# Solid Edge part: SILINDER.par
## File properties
Author: Türk
Template: iso part.par
Last saved by: Türk
Revision: 44
Application: Solid Edge
Accuracy: 0,990
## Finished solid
Body 1: sheet body, 2 faces, 150 edges, 150 vertices.
  Faces by surface: plane 2
  Edges by curve: line 102, circle 48
Body 2: sheet body, 2 faces, 76 edges, 76 vertices.
  Faces by surface: plane 2
  Edges by curve: line 52, intersection 20, circle 4
Body 3: solid body, 274 faces, 784 edges, 516 vertices.
  Faces by surface: cylinder 149, plane 101, cone 14, torus 10
  Edges by curve: line 374, circle 335, intersection 74, ellipse 1
Bounding box of the edges (mm; curved faces can reach further): 640.000 x 347.698 x 213.551, from (-320, -127.6984, -111.7187) to (320, 220, 101.8327).
Cylindrical faces by radius (mm): R7 x20, R10 x36, R15 x8, R22 x6, R44 x5, R50 x24, R70 x18, R78 x4, R80 x8, R82.5 x10, R90 x10
Conical faces (half-angle, radius in mm at the cone's reference point): 6 deg R80 x4, 45 deg R90 x10
Toroidal faces (ring radius, tube radius in mm): R77.5 r5 x10
Planar faces by outward normal: +x 18, +y 23, +z 16, -x 17, -y 4, -z 16, oblique 7
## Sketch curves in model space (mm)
line (0, 48.4062, 34.6876) -> (0, 48.4062, -36.2077)
arc centre (201, -20, 77.5) radius 5 from (201, -20, 82.5) through (197.3631, -20, 80.9312) to (196, -20, 77.5)
line (-320, -20, 58.7298) -> (-320, -20, 22)
arc centre (-201, -20, 77.5) radius 5 from (-201, -20, 82.5) through (-197.3631, -20, 80.9312) to (-196, -20, 77.5)
arc centre (39, -20, 77.5) radius 5 from (39, -20, 82.5) through (42.6369, -20, 80.9312) to (44, -20, 77.5)
line (-320, -20, -58.7298) -> (-320, -20, -22)
line (200, -20, -85) -> (200, -20, -82.399)
arc centre (201, -20, -77.5) radius 5 from (200, -20, -82.399) through (200.4975, -20, -82.4747) to (201, -20, -82.5)
line (315, -20, -24) -> (315, -20, -22)
line (315, -20, -24) -> (286, -20, -24)
line (286, -20, -24) -> (286, -20, -77.5)
arc centre (279, -20, -77.5) radius 7 from (286, -20, -77.5) through (283.8037, -20, -82.5916) to (279, -20, -84.5)
line (279, -20, -84.5) -> (201, -20, -84.5)
arc centre (201, -20, -77.5) radius 7 from (201, -20, -84.5) through (195.9084, -20, -82.3037) to (194, -20, -77.5)
line (194, -20, -77.5) -> (194, -20, -24)
line (194, -20, -24) -> (166, -20, -24)
line (166, -20, -24) -> (166, -20, -77.5)
arc centre (159, -20, -77.5) radius 7 from (166, -20, -77.5) through (163.8037, -20, -82.5916) to (159, -20, -84.5)
line (159, -20, -84.5) -> (81, -20, -84.5)
arc centre (81, -20, -77.5) radius 7 from (81, -20, -84.5) through (75.9084, -20, -82.3037) to (74, -20, -77.5)
line (74, -20, -77.5) -> (74, -20, -24)
line (74, -20, -24) -> (46, -20, -24)
line (46, -20, -24) -> (46, -20, -77.5)
arc centre (39, -20, -77.5) radius 7 from (46, -20, -77.5) through (43.8037, -20, -82.5916) to (39, -20, -84.5)
line (39, -20, -84.5) -> (-39, -20, -84.5)
arc centre (-39, -20, -77.5) radius 7 from (-39, -20, -84.5) through (-44.0916, -20, -82.3037) to (-46, -20, -77.5)
line (-46, -20, -77.5) -> (-46, -20, -24)
line (-46, -20, -24) -> (-74, -20, -24)
line (-74, -20, -24) -> (-74, -20, -77.5)
arc centre (-81, -20, -77.5) radius 7 from (-74, -20, -77.5) through (-76.1963, -20, -82.5916) to (-81, -20, -84.5)
line (-81, -20, -84.5) -> (-159, -20, -84.5)
arc centre (-159, -20, -77.5) radius 7 from (-159, -20, -84.5) through (-164.0916, -20, -82.3037) to (-166, -20, -77.5)
line (-166, -20, -77.5) -> (-166, -20, -24)
line (-166, -20, -24) -> (-194, -20, -24)
line (-194, -20, -24) -> (-194, -20, -77.5)
arc centre (-201, -20, -77.5) radius 7 from (-194, -20, -77.5) through (-196.1963, -20, -82.5916) to (-201, -20, -84.5)
line (-201, -20, -84.5) -> (-279, -20, -84.5)
arc centre (-279, -20, -77.5) radius 7 from (-279, -20, -84.5) through (-284.0916, -20, -82.3037) to (-286, -20, -77.5)
line (-286, -20, -77.5) -> (-286, -20, -24)
line (-286, -20, -24) -> (-318, -20, -24)
line (-318, -20, -24) -> (-318, -20, -58.2099)
arc centre (-250, -20, -20) radius 78 from (-318, -20, -58.2099) through (-289.393, -20, -87.3215) to (-250, -20, -98)
line (-250, -20, -98) -> (250, -20, -98)
arc centre (250, -20, -20) radius 78 from (250, -20, -98) through (286.8846, -20, -88.7279) to (315, -20, -63.1161)
line (315, -20, -66.6369) -> (315, -20, -63.1161)
line (315, -20, 63.1161) -> (315, -20, 66.6369)
arc centre (250, -20, 20) radius 78 from (250, -20, 98) through (286.8846, -20, 88.7279) to (315, -20, 63.1161)
line (-250, -20, 98) -> (250, -20, 98)
arc centre (-250, -20, 20) radius 78 from (-318, -20, 58.2099) through (-289.393, -20, 87.3215) to (-250, -20, 98)
line (-318, -20, 24) -> (-318, -20, 58.2099)
line (-286, -20, 24) -> (-318, -20, 24)
line (-286, -20, 77.5) -> (-286, -20, 24)
arc centre (-279, -20, 77.5) radius 7 from (-279, -20, 84.5) through (-284.0916, -20, 82.3037) to (-286, -20, 77.5)
line (-201, -20, 84.5) -> (-279, -20, 84.5)
arc centre (-201, -20, 77.5) radius 7 from (-194, -20, 77.5) through (-196.1963, -20, 82.5916) to (-201, -20, 84.5)
line (-194, -20, 24) -> (-194, -20, 77.5)
line (-166, -20, 24) -> (-194, -20, 24)
line (-166, -20, 77.5) -> (-166, -20, 24)
arc centre (-159, -20, 77.5) radius 7 from (-159, -20, 84.5) through (-164.0916, -20, 82.3037) to (-166, -20, 77.5)
line (-81, -20, 84.5) -> (-159, -20, 84.5)
arc centre (-81, -20, 77.5) radius 7 from (-74, -20, 77.5) through (-76.1963, -20, 82.5916) to (-81, -20, 84.5)
line (-74, -20, 24) -> (-74, -20, 77.5)
line (-46, -20, 24) -> (-74, -20, 24)
line (-46, -20, 77.5) -> (-46, -20, 24)
arc centre (-39, -20, 77.5) radius 7 from (-39, -20, 84.5) through (-44.0916, -20, 82.3037) to (-46, -20, 77.5)
line (39, -20, 84.5) -> (-39, -20, 84.5)
arc centre (39, -20, 77.5) radius 7 from (46, -20, 77.5) through (43.8037, -20, 82.5916) to (39, -20, 84.5)
line (46, -20, 24) -> (46, -20, 77.5)
line (74, -20, 24) -> (46, -20, 24)
line (74, -20, 77.5) -> (74, -20, 24)
arc centre (81, -20, 77.5) radius 7 from (81, -20, 84.5) through (75.9084, -20, 82.3037) to (74, -20, 77.5)
line (159, -20, 84.5) -> (81, -20, 84.5)
arc centre (159, -20, 77.5) radius 7 from (166, -20, 77.5) through (163.8037, -20, 82.5916) to (159, -20, 84.5)
line (166, -20, 24) -> (166, -20, 77.5)
line (194, -20, 24) -> (166, -20, 24)
line (194, -20, 77.5) -> (194, -20, 24)
arc centre (201, -20, 77.5) radius 7 from (201, -20, 84.5) through (195.9084, -20, 82.3037) to (194, -20, 77.5)
line (279, -20, 84.5) -> (201, -20, 84.5)
arc centre (279, -20, 77.5) radius 7 from (286, -20, 77.5) through (283.8037, -20, 82.5916) to (279, -20, 84.5)
line (286, -20, 24) -> (286, -20, 77.5)
line (315, -20, 24) -> (286, -20, 24)
line (315, -20, 22) -> (315, -20, 24)
arc centre (0, 145, 0) radius 80 from (-60, 145, -52.915) through (2.3391, 145, -79.9658) to (60, 145, -52.915)
arc centre (0, 145, 0) radius 80 from (60, 145, -52.915) through (-2.3391, 145, -79.9658) to (-60, 145, -52.915)
arc centre (0, 145, 0) radius 80 from (60, 145, 52.915) through (-2.3391, 145, 79.9658) to (-60, 145, 52.915)
arc centre (0, 145, 0) radius 80 from (60, 145, -52.915) through (-2.3391, 145, -79.9658) to (-60, 145, -52.915)
arc centre (0, 145, 0) radius 80 from (-60, 145, -52.915) through (2.3391, 145, -79.9658) to (60, 145, -52.915)
arc centre (0, 145, 0) radius 80 from (-60, 145, 52.915) through (2.3391, 145, 79.9658) to (60, 145, 52.915)
arc centre (-120, 145, 0) radius 80 from (-180, 145, -52.915) through (-117.6609, 145, -79.9658) to (-60, 145, -52.915)
arc centre (-120, 145, 0) radius 80 from (-60, 145, 52.915) through (-122.3391, 145, 79.9658) to (-180, 145, 52.915)
arc centre (-240, 145, 0) radius 80 from (-180, 145, 52.915) through (-319.4299, 145, -9.5333) to (-180, 145, -52.915)
arc centre (120, 145, 0) radius 80 from (180, 145, -52.915) through (117.6609, 145, -79.9658) to (60, 145, -52.915)
arc centre (120, 145, 0) radius 80 from (60, 145, 52.915) through (122.3391, 145, 79.9658) to (180, 145, 52.915)
arc centre (240, 145, 0) radius 80 from (180, 145, 52.915) through (319.4299, 145, -9.5333) to (180, 145, -52.915)
line (-320, -20, 0) -> (-320, 71.59, 0)
line (-320, 71.59, 0) -> (-320, 71.59, -19.9042)
line (-320, 110, 0) -> (-320, 155, 0)
line (-320, 71.59, 0) -> (-320, 110, 0)
line (270, 0, 0) -> (270, -50.7773, 108.8922)
arc centre (-244.8082, 0, 20) radius 44 from (-284, 0, 0) through (-234.5232, 0, -22.7811) to (-200.8082, 0, 20)
arc centre (240, 0, 0) radius 44 from (196, 0, 0) through (241.3039, 0, -43.9807) to (284, 0, 0)
arc centre (120, 0, 0) radius 44 from (80.8082, 0, 20) through (77.2189, 0, 10.2849) to (76, 0, 0)
arc centre (-120, 0, 0) radius 44 from (-76, 0, 0) through (-77.2189, 0, 10.2849) to (-80.8082, 0, 20)
arc centre (0, 0, 0) radius 44 from (44, 0, 0) through (42.7811, 0, 10.2849) to (39.1918, 0, 20)
arc centre (120, 0, 0) radius 80 from (60, 0, -52.915) through (122.3391, 0, -79.9658) to (180, 0, -52.915)
arc centre (-240, 0, 0) radius 80 from (-180, 0, -52.915) through (-319.4299, 0, 9.5333) to (-180, 0, 52.915)
arc centre (-120, 0, 0) radius 80 from (-60, 0, -52.915) through (-122.3391, 0, -79.9658) to (-180, 0, -52.915)
arc centre (0, 0, 0) radius 80 from (0, 0, -80) through (-32.915, 0, -72.915) to (-60, 0, -52.915)
arc centre (0, 0, 0) radius 80 from (0, 0, -80) through (32.915, 0, -72.915) to (60, 0, -52.915)
circle centre (-240, 0, 0) radius 44.5
circle centre (-120, 0, 0) radius 44.5
circle centre (-240, 0, 0) radius 47.5
circle centre (-120, 0, 0) radius 47.5
circle centre (240, 0, 0) radius 44.5
circle centre (120, 0, 0) radius 44.5
circle centre (240, 0, 0) radius 47.5
circle centre (120, 0, 0) radius 47.5
line (0, 0, 44.5) -> (0, 0, 44)
line (0, 0, 44.5) -> (0, 0, 44)
arc centre (0, 0, 0) radius 44.5 from (0, 0, -44.5) through (-44.4805, 0, 1.3187) to (0, 0, 44.5)
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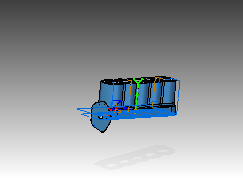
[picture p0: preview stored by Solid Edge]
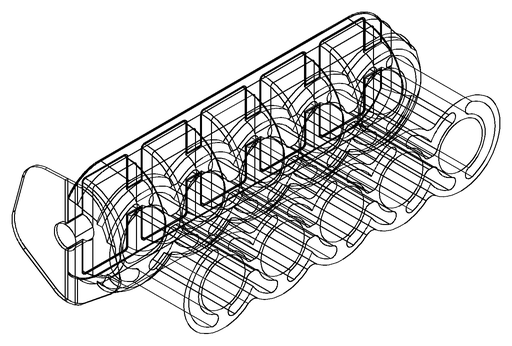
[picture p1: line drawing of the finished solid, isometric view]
